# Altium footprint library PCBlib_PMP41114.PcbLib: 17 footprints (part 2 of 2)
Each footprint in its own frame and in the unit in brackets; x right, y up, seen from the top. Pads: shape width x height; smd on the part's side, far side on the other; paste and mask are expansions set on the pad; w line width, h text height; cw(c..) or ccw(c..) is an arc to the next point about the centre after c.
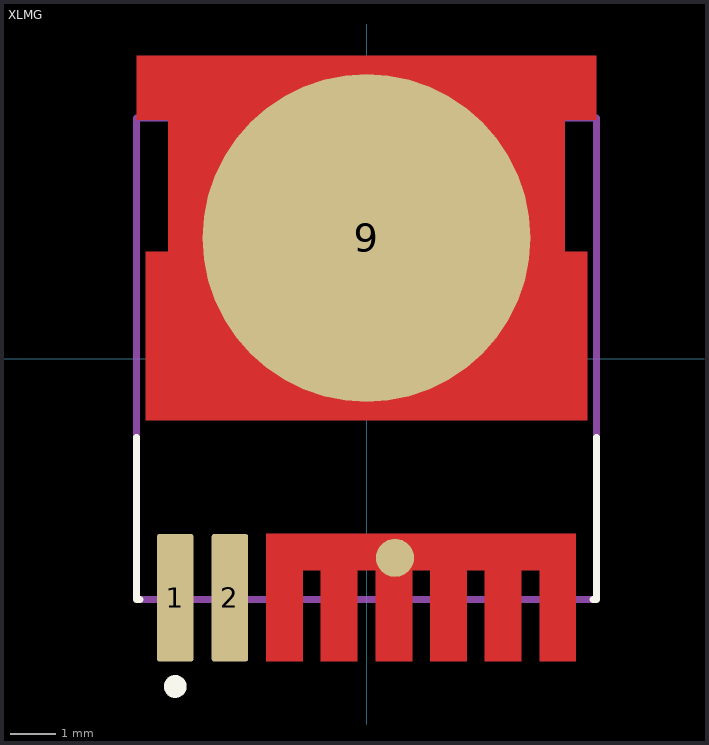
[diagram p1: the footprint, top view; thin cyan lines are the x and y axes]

## XLMG [mm]
height 7.8
pads (4):
  rrect13% 0.8x2.8 smd paste-1000 mask+0: 1(-4.2,-5.25) 2(-3,-5.25)
  round 0.837 smd paste-1000 mask+0: 2-3-4-5-6-7-8(0.625,-4.375)
  round 7.2 smd paste-1000 mask+0: 9(0,2.65)
Top Layer:
  region: -5.05,6.65 5.05,6.65 5.05,5.25 4.35,5.25 4.35,2.35 4.85,2.35 4.85,-1.35 -4.85,-1.35 -4.85,2.35 -4.35,2.35 -4.35,5.25 -5.05,5.25
  region: -2.2,-3.85 4.6,-3.85 4.6,-6.65 3.8,-6.65 3.8,-4.65 3.4,-4.65 3.4,-6.65 2.6,-6.65 2.6,-4.65 2.2,-4.65 2.2,-6.65 1.4,-6.65 1.4,-4.65 1,-4.65 1,-6.65 0.2,-6.65 0.2,-4.65 -0.2,-4.65 -0.2,-6.65 -1,-6.65 -1,-4.65 -1.4,-4.65 -1.4,-6.65 -2.2,-6.65 -2.2,-4.65
Top Overlay:
  circle w0.25: c-4.2,-7.2 r0.125
  lines w0.15: -5.05,-1.725 -5.05,-5.288 -4.975,-5.288 ; 4.975,-5.288 5.05,-5.288 5.05,-1.725
Top Paste:
  drawing of 50 lines, arcs and shapes, not listed
Mechanical 5:
  lines w0.15: -5.05,-5.288 5.05,-5.288 5.05,5.288 -5.05,5.288 -5.05,-5.288
  text ".Designator" at 0.05,0.217 h0.5
3D body "Trans_IAUT300N10S5N015ATMA1_HSOF-8.STEP": height 0.25, standoff 0, extent -5.15,-6.75 5.15,6.75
